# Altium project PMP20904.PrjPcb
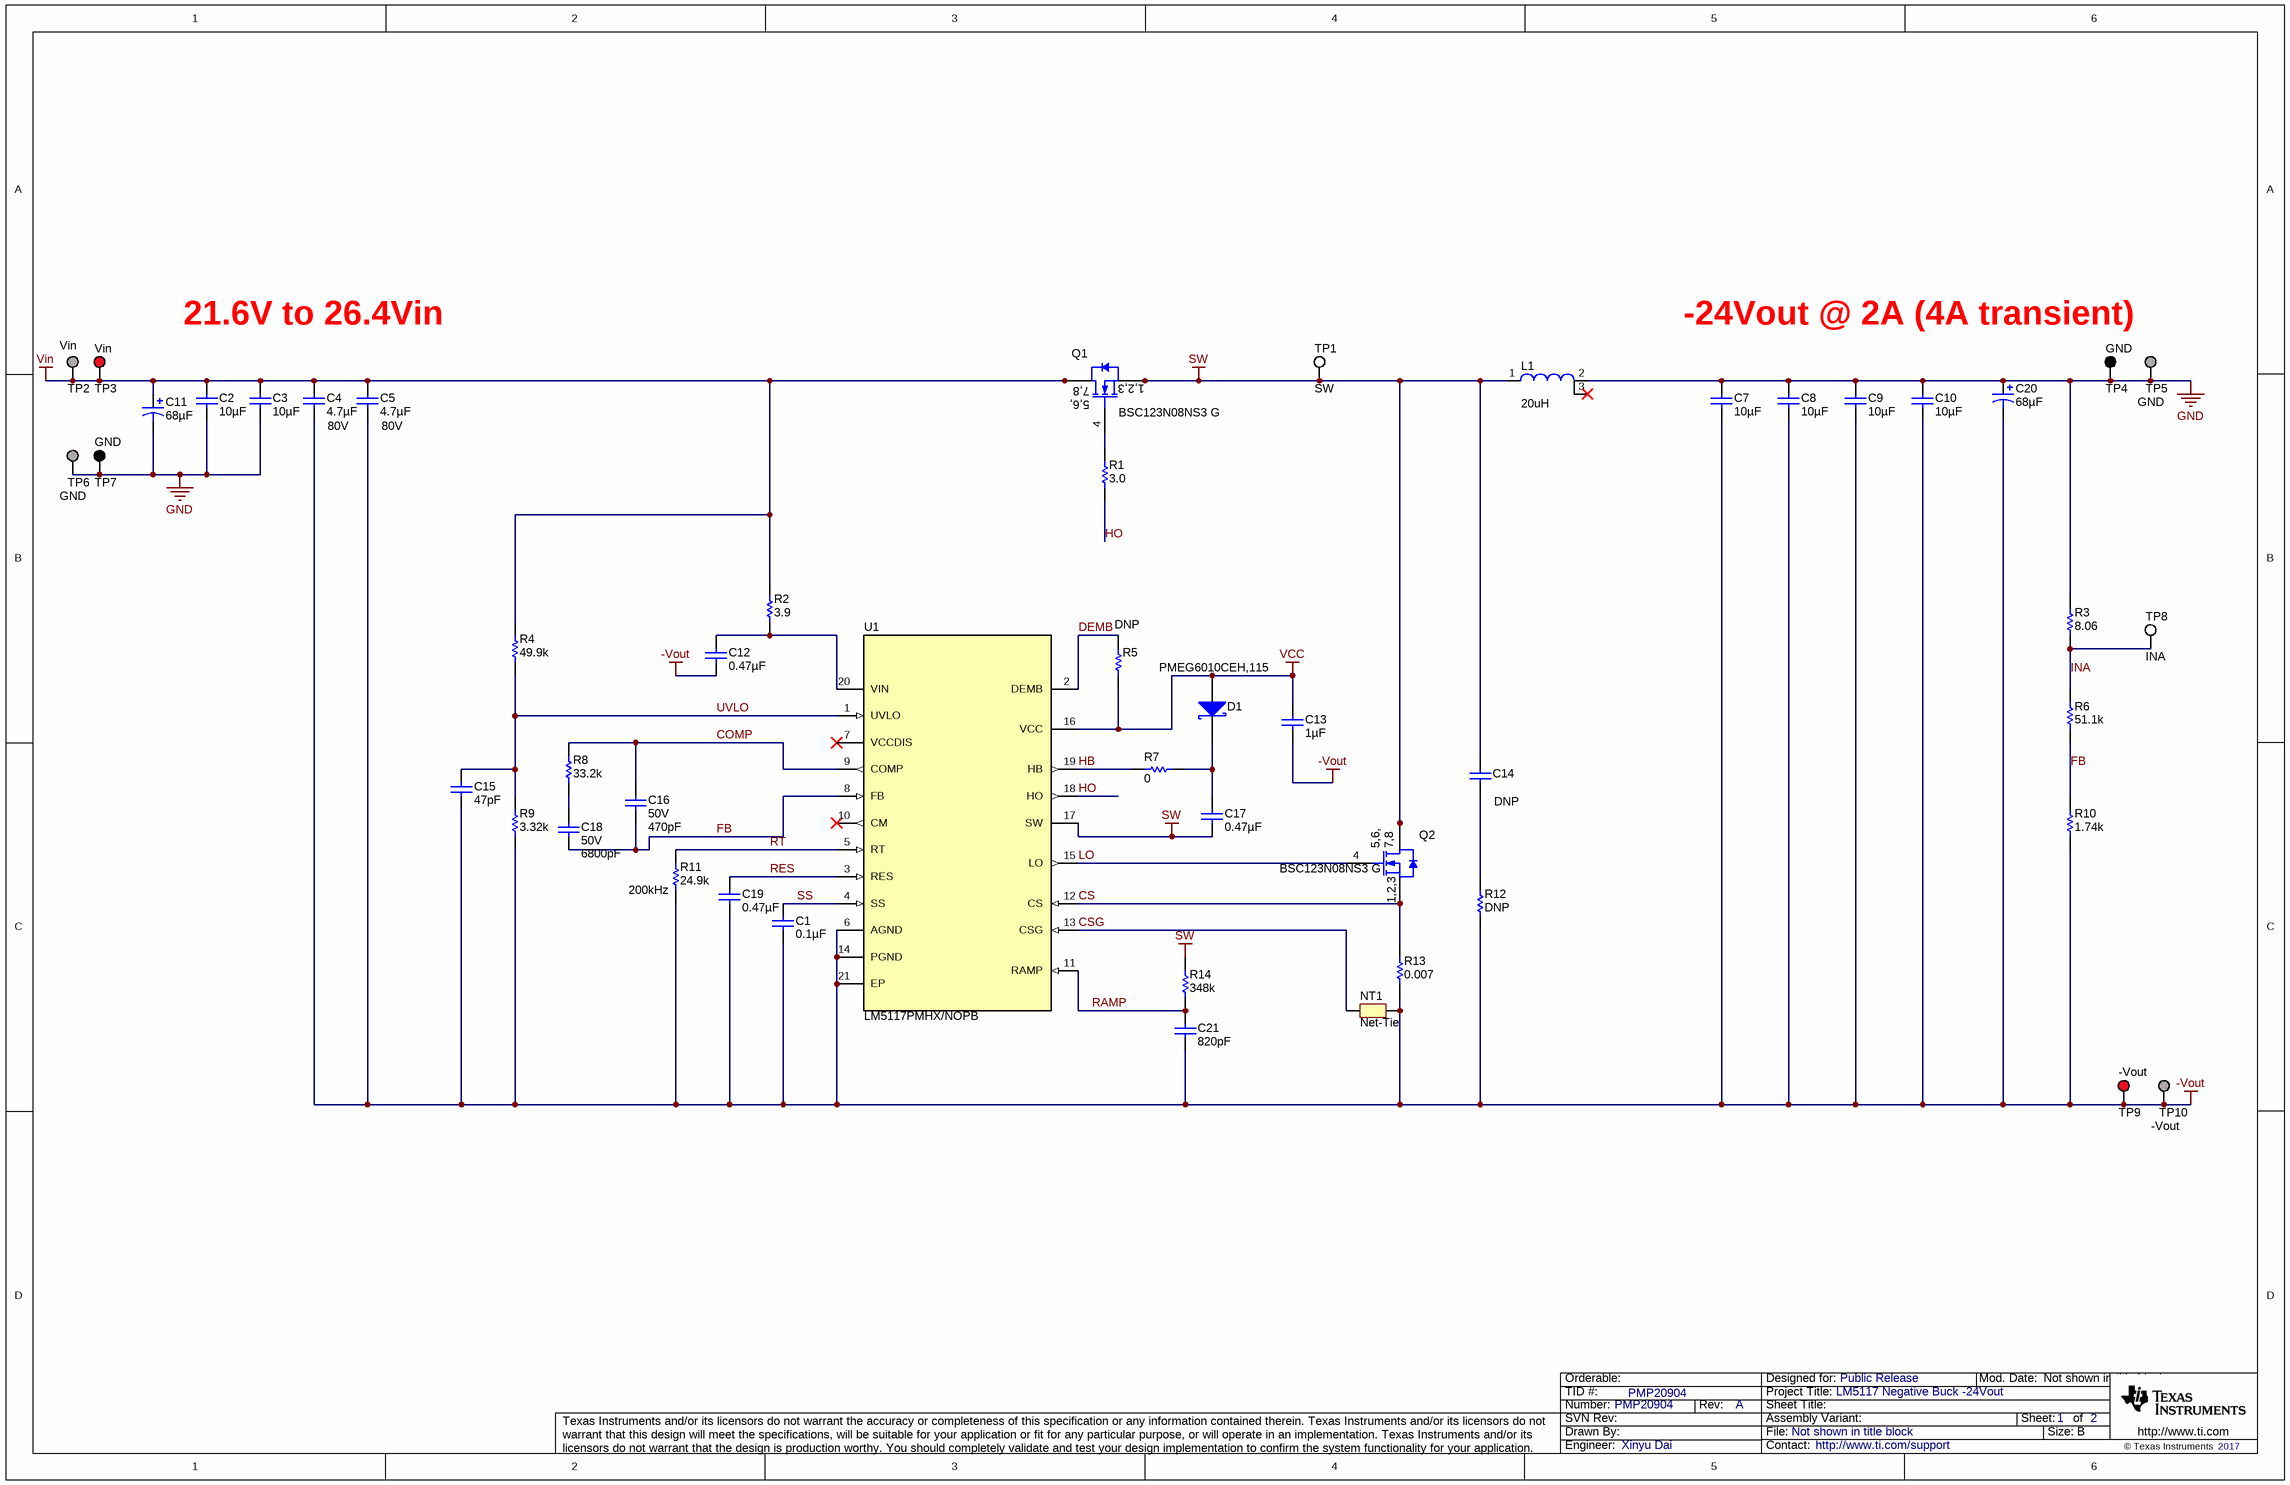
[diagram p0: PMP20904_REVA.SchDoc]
TID: PMP20904; TechSupport: http://www.ti.com/support; SCH_Rev: A; PRJ_Title: LM5117 Negative Buck -24Vout; PRJ_Number: PMP20904; PRJ_Engineer: Xinyu Dai; PRJ_Customer: Public Release; PCB_Rev: A; PCB_Layout: Xinyu Dai; CopyrightYear: 2017
2 sheets, 64 parts. Net scope: global (net labels, ports and power ports of the same name join across sheets).
Board file: PMP20904_REVA.PcbDoc
Sheets:
  PMP20904_REVA.SchDoc
  PMP20904_REVA_Hardware.SchDoc

## Sheet PMP20904_REVA.SchDoc
size 431 x 279 mm; Date: Not shown in title block; ApprovedBy: Not shown in title block; CheckedBy: Not shown in title block; Author: Not shown in title block; CompanyName: Not shown in title block; Engineer: Not shown in title block; Organization: Not shown in title block; Address1: Not shown in title block; Address2: Not shown in title block; Address3: Not shown in title block; Address4: Not shown in title block; DocumentNumber: 1; Revision: Use project parameter SCH_Rev; SheetNumber: 1; SheetTotal: 2; PageSetup: Record=PageOptions¦CenterHorizontal=True¦CenterVertical=True¦PrintScale=1.00¦XCorrection=1.00¦YCorrection=1.00¦PrintKind=0¦BorderSize=5000000¦LeftOffset=0¦BottomOffset=0¦Orientation=2¦PaperLength=1000¦PaperWidth=1000¦Scale=100¦PaperSource=15¦PrintQuality=600¦MediaType=1¦DitherType=10¦PaperKind=Letter¦PrintScaleMode=1

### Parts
C1  ValueDisplayed: 0.1µF  [0603L]  (hidden comment: GRM188R71E104KA01D)
C2  ValueDisplayed: 10µF  [1210L]  (hidden comment: UMK325AB7106KM-T)
C3  ValueDisplayed: 10µF  [1210L]  (hidden comment: UMK325AB7106KM-T)
C4  ValueDisplayed: 4.7µF  Value2: 80V  [1210L]  (hidden comment: GRM32ER71K475KE14L)
C5  ValueDisplayed: 4.7µF  Value2: 80V  [1210L]  (hidden comment: GRM32ER71K475KE14L)
C7  ValueDisplayed: 10µF  [1210L]  (hidden comment: UMK325AB7106KM-T)
C8  ValueDisplayed: 10µF  [1210L]  (hidden comment: UMK325AB7106KM-T)
C9  ValueDisplayed: 10µF  [1210L]  (hidden comment: UMK325AB7106KM-T)
C10  ValueDisplayed: 10µF  [1210L]  (hidden comment: UMK325AB7106KM-T)
C11  ValueDisplayed: 68µF  [SM_RADIAL_6.3BMM]  (hidden comment: UUD1V680MCL1GS)
C12  ValueDisplayed: 0.47µF  [0603L]  (hidden comment: CGA3E3X7R1H474M080AE)
C13  ValueDisplayed: 1µF  [0603L]  (hidden comment: GRM188R71C105KE15D)
C14  DNP  [0805L]
C15  ValueDisplayed: 47pF  [0603L]  (hidden comment: GRM1885C1H470JA01D)
C16  VDC_V: 50V  ValueDisplayed: 470pF  [0603L]  (hidden comment: GRM1885C1H471JA01D)
C17  ValueDisplayed: 0.47µF  [0603L]  (hidden comment: CGA3E3X7R1H474M080AE)
C18  VDC_V: 50V  ValueDisplayed: 6800pF  [0603L]  (hidden comment: GRM188R71H682KA01D)
C19  ValueDisplayed: 0.47µF  [0603L]  (hidden comment: CGA3E3X7R1H474M080AE)
C20  ValueDisplayed: 68µF  [SM_RADIAL_6.3BMM]  (hidden comment: UUD1V680MCL1GS)
C21  ValueDisplayed: 820pF  [0603L]  (hidden comment: GRM1885C1H821JA01D)
D1  PMEG6010CEH,115  [SOD-123F]
L1  ValueDisplayed: 20uH  [B82559_1420]  (hidden comment: B82559A203A20)
NT1  Net-Tie  [Net-Tie_10mil]  (net tie, no BOM)
Q1  BSC123N08NS3 G  [PG-TDSON-8]
Q2  BSC123N08NS3 G  [PG-TDSON-8]
R1  ValueDisplayed: 3.0  [0603L]  (hidden comment: CRCW06033R00JNEA)
R2  ValueDisplayed: 3.9  [0603L]  (hidden comment: CRCW06033R90JNEA)
R3  ValueDisplayed: 8.06  [0603L]  (hidden comment: CRCW06038R06FKEA)
R4  ValueDisplayed: 49.9k  [0603L]  (hidden comment: CRCW060349K9FKEA)
R5  DNP  [0603L]
R6  ValueDisplayed: 51.1k  [0603L]  (hidden comment: CRCW060351K1FKEA)
R7  ValueDisplayed: 0  [0603L]  (hidden comment: CRCW06030000Z0EA)
R8  ValueDisplayed: 33.2k  [0603L]  (hidden comment: CRCW060333K2FKEA)
R9  ValueDisplayed: 3.32k  [0603L]  (hidden comment: CRCW06033K32FKEA)
R10  ValueDisplayed: 1.74k  [0603]  (hidden comment: CRCW06031K74FKEA)
R11  ValueDisplayed: 24.9k  [0603L]  (hidden comment: CRCW060324K9FKEA)
R12  DNP  [1206L]
R13  ValueDisplayed: 0.007  [PE1206]  (hidden comment: PE1206FRF470R007L)
R14  ValueDisplayed: 348k  [0603L]  (hidden comment: CRCW0603348KFKEA)
TP1  SW  [Keystone5002]
TP2  Vin  [Keystone1502-2]
TP3  Vin  [Keystone5000]
TP4  GND  [Keystone5001]
TP5  GND  [Keystone1502-2]
TP6  GND  [Keystone1502-2]
TP7  GND  [Keystone5001]
TP8  INA  [Keystone5002]
TP9  -Vout  [Keystone5000]
TP10  -Vout  [Keystone1502-2]
U1  LM5117PMHX/NOPB  [PWP0020A_N]

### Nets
-Vout: C1.2 C4.2 C5.2 C7.2 C8.2 C9.2 C10.2 C12.2 C13.2 C15.2 C19.2 C20.2(-) C21.2 NT1.1 R9.1 R10.1 R11.1 R12.1 R13.1 TP9.1 TP10.1 U1.6(AGND) U1.14(PGND) U1.21(EP)
GND: C2.2 C3.2 C7.1 C8.1 C9.1 C10.1 C11.2(-) C20.1(+) L1.2 R3.2 TP4.1 TP5.1 TP6.1 TP7.1
SW: C14.1 C17.2 L1.1 Q1.1(S) Q1.2(S) Q1.3(S) Q2.5(D) Q2.6(D) Q2.7(D) Q2.8(D) Q2.9(D) R14.2 TP1.1 U1.17(SW)
VCC: C13.1 D1.2(A) R5.1 U1.16(VCC)
Vin: C2.1 C3.1 C4.1 C5.1 C11.1(+) Q1.5(D) Q1.6(D) Q1.7(D) Q1.8(D) Q1.9(D) R2.2 R4.2 TP2.1 TP3.1
COMP: C16.1 R8.1 U1.9(COMP)
CS: Q2.1(S) Q2.2(S) Q2.3(S) R13.2 U1.12(CS)
CSG: NT1.2 U1.13(CSG)
DEMB: R5.2 U1.2(DEMB)
FB: C16.2 C18.2 R6.1 R10.2 U1.8(FB)
HB: R7.2 U1.19(HB)
HO: R1.1 U1.18(HO)
INA: R3.1 R6.2 TP8.1
LO: Q2.4(G) U1.15(LO)
RAMP: C21.1 R14.1 U1.11(RAMP)
RES: C19.1 U1.3(RES)
RT: R11.2 U1.5(RT)
SS: C1.1 U1.4(SS)
UVLO: C15.1 R4.1 R9.2 U1.1(UVLO)
NetC12_1: C12.1 R2.1 U1.20(VIN)
NetC14_2: C14.2 R12.2
NetC17_1: C17.1 D1.1(K) R7.1
NetC18_1: C18.1 R8.2
NetQ1_4: Q1.4(G) R1.2

Not connected (* = marked no-connect by the designer): L1 3*; U1 7(VCCDIS)* 10(CM)*

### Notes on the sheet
- 21.6V to 26.4Vin
- -24Vout @ 2A (4A transient)
- (near R11) 200kHz

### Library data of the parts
C1 = GRM188R71E104KA01D: CAP, CERM, 0.1 µF, 25 V, +/- 10%, X7R, 0603; Manufacturer: MuRata; Polarized: N; CompType: Capacitor; Value: 0.1uF; U/M: EA; Cap_F: 0.0000001; Tolerance_%: 10; Value1: Unknown; VDC_V: 25; Value2: 25V; TaMin_C: -55; TaMax_C: 125; Cap_Case: 0603; SizeArea_mm2: 1.28; SizeAreaWB_mm2: 4.68; SizeX_mm: 1.6; SizeY_mm: 0.8; SizeZ_mm: 1; AEC Category: Q200
C2 C3 C7-C10 = UMK325AB7106KM-T: CAP, CERM, 10 µF, 50 V, +/- 10%, X7R, 1210; Manufacturer: Taiyo Yuden; Polarized: N; CompType: Capacitor; Value: 10uF; U/M: EA; Cap_F: 0.00001; Tolerance_%: 10; Value1: Unknown; VDC_V: 50; Value2: 50V; TaMin_C: -55; TaMax_C: 125; Cap_Case: 1210; SizeArea_mm2: 8; SizeAreaWB_mm2: 14.7; SizeX_mm: 3.2; SizeY_mm: 2.5; SizeZ_mm: 2.8; AEC Category: Q200
C4 C5 = GRM32ER71K475KE14L: CAP, CERM, 4.7 µF, 80 V, +/- 10%, X7R, 1210; Manufacturer: MuRata; Polarized: N; CompType: Capacitor; Value: 4.7uF; U/M: EA; Cap_F: 0.0000047; Tolerance_%: 10; Value1: Unknown; VDC_V: 80; TaMin_C: -55; TaMax_C: 125; Cap_Case: 1210; SizeArea_mm2: 8; SizeAreaWB_mm2: 14.7; SizeX_mm: 3.2; SizeY_mm: 2.5; SizeZ_mm: 2.7; AEC Category: Q200
C11 C20 = UUD1V680MCL1GS: CAP, AL, 68 µF, 35 V, +/- 20%, 0.34 ohm, SMD; Manufacturer: Nichicon; Polarized: Y; CompType: Capacitor; Value: 68uF; U/M: EA; Cap_F: 0.000068; Tolerance_%: 20; VDC_V: 35; Value2: 35V; ESR_ohm: 0.34; IRMS_A: 0.28; TaMin_C: -55; TaMax_C: 105; Cap_Case: 6.3x7.7; SizeAreaWB_mm2: 79.98; SizeArea_mm2: 48.18; SizeX_mm: 7.3; SizeY_mm: 6.6; SizeZ_mm: 7.7; AEC Category: Q200
C12 C17 C19 = CGA3E3X7R1H474M080AE: CAP, CERM, 0.47 µF, 50 V, +/- 20%, X7R, AEC-Q200 Grade 1, 0603; Manufacturer: TDK; Polarized: N; CompType: Capacitor; Value: 0.47uF; U/M: EA; Cap_F: 0.00000047; Tolerance_%: 20; Value1: Unknown; VDC_V: 50; Value2: 50V; TaMin_C: -55; TaMax_C: 125; Cap_Case: 0603; SizeArea_mm2: 1.28; SizeAreaWB_mm2: 4.68; SizeX_mm: 1.6; SizeY_mm: 0.8; SizeZ_mm: 1; AEC Category: Q200; AEC Qualified: Y
C13 = GRM188R71C105KE15D: CAP, CERM, 1 µF, 16 V, +/- 10%, X7R, 0603; Manufacturer: MuRata; Polarized: N; CompType: Capacitor; Value: 1uF; U/M: EA; Cap_F: 0.000001; Tolerance_%: 10; Value1: Unknown; VDC_V: 16; Value2: 16V; TaMin_C: -55; TaMax_C: 125; Cap_Case: 0603; SizeArea_mm2: 1.28; SizeAreaWB_mm2: 4.68; SizeX_mm: 1.6; SizeY_mm: 0.8; SizeZ_mm: 1; AEC Category: Q200
C14 = GRM2165C2A101JA01D: CAP, CERM, 100 pF, 100 V, +/- 5%, C0G/NP0, 0805; Manufacturer: MuRata; Polarized: N; CompType: Capacitor; Value: 100pF; U/M: EA; Cap_F: 0.0000000001; Tolerance_%: 5; Value1: Unknown; VDC_V: 100; Value2: 100V; TaMin_C: -55; TaMax_C: 125; Cap_Case: 0805; SizeArea_mm2: 2.5; SizeAreaWB_mm2: 6.75; SizeX_mm: 2; SizeY_mm: 1.25; SizeZ_mm: 1.45; AEC Category: Q200
C15 = GRM1885C1H470JA01D: CAP, CERM, 47 pF, 50 V, +/- 5%, C0G/NP0, 0603; Manufacturer: MuRata; Polarized: N; CompType: Capacitor; Value: 47pF; U/M: EA; Cap_F: 0.000000000047; Tolerance_%: 5; Value1: Unknown; VDC_V: 50; Value2: 50V; TaMin_C: -55; TaMax_C: 125; Cap_Case: 0603; SizeArea_mm2: 1.28; SizeAreaWB_mm2: 4.68; SizeX_mm: 1.6; SizeY_mm: 0.8; SizeZ_mm: 1; AEC Category: Q200
C16 = CMP-0007221-2: CAP, CERM, 470 pF, 50 V, +/- 5%, C0G/NP0, 0603; Manufacturer: MuRata; TaMin_C: -55°C; Polarized: N; SizeAreaWB_mm2: 4.68; Value1: Unknown; U/M: EA; Value: 470pF; TaMax_C: 125°C; SizeZ_mm: 1; SizeX_mm: 1.6; SizeY_mm: 0.8; Cap_Case: 0603; SizeArea_mm2: 1.28; CompType: Capacitor; AEC Category: Q200
C18 = CMP-0007462-2: CAP, CERM, 6800 pF, 50 V, +/- 10%, X7R, 0603; Manufacturer: MuRata; TaMin_C: -55°C; Polarized: N; SizeAreaWB_mm2: 4.68; Value1: Unknown; U/M: EA; Value: 6800pF; TaMax_C: 125°C; SizeZ_mm: 1; SizeX_mm: 1.6; SizeY_mm: 0.8; Cap_Case: 0603; SizeArea_mm2: 1.28; CompType: Capacitor; Cap_F: 6.8nF; AEC Category: Q200
C21 = GRM1885C1H821JA01D: CAP, CERM, 820 pF, 50 V, +/- 5%, C0G/NP0, 0603; Manufacturer: MuRata; Polarized: N; CompType: Capacitor; Value: 820pF; U/M: EA; Cap_F: 0.00000000082; Tolerance_%: 5; Value1: Unknown; VDC_V: 50; Value2: 50V; TaMin_C: -55; TaMax_C: 125; Cap_Case: 0603; SizeArea_mm2: 1.28; SizeAreaWB_mm2: 4.68; SizeX_mm: 1.6; SizeY_mm: 0.8; SizeZ_mm: 1; AEC Category: Q200
D1 = PMEG6010CEH,115: Diode, Schottky, 60 V, 1 A, SOD-123F; Manufacturer: Nexperia; U/M: EA; Vf_V: 0.57; Value: 60V; Value1: 1A; Value2: 0.57V; Io_A: 1; Vr_V: 60; TJmax_C: 150; SizeAreaWB_mm2: 11.7; SizeArea_mm2: 5.6; SizeX_mm: 3.5; SizeY_mm: 1.6; SizeZ_mm: 1.1; AEC Category: Q101
L1 = CMP-0062443-2: Inductor, Wirewound, Ferrite, 20 uH, 14.3 A, 0.0064 ohm, AEC-Q200 Grade 0, SMD; Manufacturer: TDK; Isat: 14.3A @ 10% inductance drop; Green_Lifecycle: Not Set; SizeAreaWB_mm2: 583.2; DCR_ohm: 6.4m; Green_REACh: Incomplete; Value: 20uH; Imax_A: 14.3A; SizeZ_mm: 14.5; SizeX_mm: 22; SizeY_mm: 22.3; SizeArea_mm2: 490.6; Ind_H: 20µH; AEC Qualified: Y; AEC Grade: 0; AEC Category: Q200
NT1 = Net-Tie: Single point connection between nets.; SymbolCreator: codlsc
Q1 Q2 = BSC123N08NS3 G: MOSFET, N-CH, 80 V, 55 A, PG-TDSON-8; Manufacturer: Infineon Technologies; Alternate Manufacturer: None; U/M: EA; ChType: N; Value: 80V; VdsMax_V: 80; Value1: ? ohm; Value2: 19 nC; QgTyp_nC: 19; Vgs_V: 20; IdsMax_A: 55; SizeAreaWB_mm2: 55.131; SizeArea_mm2: 29.351; SizeX_mm: 5.99; SizeY_mm: 4.9; SizeZ_mm: 1.12; AEC Category: Q101; Green_Lifecycle: Active; Green_REACh: Passed
R1 = CRCW06033R00JNEA: RES, 3.0, 5%, 0.1 W, 0603; Manufacturer: Vishay-Dale; CompType: Resistor; Value: 3.0; Res_ohm: 3; Value_Code: 3R00; Tolerance_%: 5; Power_W: 0.1; Value2: 0.1W; VDC_V: 75; TempCo: 200 ppm/C; SizeArea_mm2: 1.28; SizeX_mm: 1.6; SizeY_mm: 0.8; SizeZ_mm: 1; EIA_Code: E24; U/M: EA; AEC Category: Q200; Green_Lifecycle: Active; Green_REACh: Passed
R2 = CRCW06033R90JNEA: RES, 3.9, 5%, 0.1 W, 0603; Manufacturer: Vishay-Dale; CompType: Resistor; Value: 3.9; Value_Code: 3R90; Tolerance_%: 5; Power_W: 0.1; Value2: 0.1W; VDC_V: 75; TempCo: 200 ppm/C; SizeArea_mm2: 1.28; SizeX_mm: 1.6; SizeY_mm: 0.8; SizeZ_mm: 1; EIA_Code: E24; U/M: EA; AEC Category: Q200
R3 = CRCW06038R06FKEA: RES, 8.06, 1%, 0.1 W, 0603; Manufacturer: Vishay-Dale; CompType: Resistor; Value: 8.06; Value_Code: 8R06; Tolerance_%: 1; Power_W: 0.1; Value2: 0.1W; VDC_V: 75; TempCo: 100 ppm/C; SizeArea_mm2: 1.28; SizeX_mm: 1.6; SizeY_mm: 0.8; EIA_Code: E96; U/M: EA; AEC Category: Q200
R4 R5 = CRCW060349K9FKEA: RES, 49.9 k, 1%, 0.1 W, 0603; Manufacturer: Vishay-Dale; CompType: Resistor; Value: 49.9k; Res_ohm: 49900; Value_Code: 49k9; Tolerance_%: 1; Power_W: 0.1; Value2: 0.1W; VDC_V: 75; TempCo: 100 ppm/C; SizeArea_mm2: 1.28; SizeX_mm: 1.6; SizeY_mm: 0.8; EIA_Code: E96; U/M: EA; AEC Category: Q200
R6 = CRCW060351K1FKEA: RES, 51.1 k, 1%, 0.1 W, 0603; Manufacturer: Vishay-Dale; CompType: Resistor; Value: 51.1k; Res_ohm: 51100; Value_Code: 51k1; Tolerance_%: 1; Power_W: 0.1; Value2: 0.1W; VDC_V: 75; TempCo: 100 ppm/C; SizeArea_mm2: 1.28; SizeX_mm: 1.6; SizeY_mm: 0.8; EIA_Code: E96; U/M: EA; AEC Category: Q200; Green_Lifecycle: Active; Green_REACh: Passed
R7 = CRCW06030000Z0EA: RES, 0, 5%, 0.1 W, 0603; Manufacturer: Vishay-Dale; CompType: Resistor; Value: 0; Value_Code: 0000; Tolerance_%: 5; Power_W: 0.1; Value2: 0.1W; VDC_V: 75; TempCo: 200 ppm/C; SizeArea_mm2: 1.28; SizeX_mm: 1.6; SizeY_mm: 0.8; SizeZ_mm: 1; EIA_Code: E24; U/M: EA; AEC Category: Q200; Green_Lifecycle: Active; Green_REACh: Passed
R8 = CRCW060333K2FKEA: RES, 33.2 k, 1%, 0.1 W, 0603; Manufacturer: Vishay-Dale; CompType: Resistor; Value: 33.2k; Res_ohm: 33200; Value_Code: 33k2; Tolerance_%: 1; Power_W: 0.1; Value2: 0.1W; VDC_V: 75; TempCo: 100 ppm/C; SizeArea_mm2: 1.28; SizeX_mm: 1.6; SizeY_mm: 0.8; EIA_Code: E96; U/M: EA; AEC Category: Q200; Green_Lifecycle: Active; Green_REACh: Passed
R9 = CRCW06033K32FKEA: RES, 3.32 k, 1%, 0.1 W, 0603; Manufacturer: Vishay-Dale; CompType: Resistor; Value: 3.32k; Res_ohm: 3320; Value_Code: 3k32; Tolerance_%: 1; Power_W: 0.1; Value2: 0.1W; VDC_V: 75; TempCo: 100 ppm/C; SizeArea_mm2: 1.28; SizeX_mm: 1.6; SizeY_mm: 0.8; EIA_Code: E96; U/M: EA; AEC Category: Q200
R10 = CRCW06031k74FKEA: RES, 1.74 k, 1%, 0.1 W, 0603; Manufacturer: Vishay-Dale; CompType: Resistor; Value: 1.74k; Res_ohm: 1740; Value_Code: 1k74; Tolerance_%: 1; Power_W: 0.1; Value2: 0.1W; VDC_V: 75; TempCo: 100 ppm/C; SizeArea_mm2: 1.28; SizeX_mm: 1.6; SizeY_mm: 0.8; EIA_Code: E96; U/M: EA; AEC Category: Q200; Green_Lifecycle: Active; Green_REACh: Passed
R11 = CRCW060324K9FKEA: RES, 24.9 k, 1%, 0.1 W, 0603; Manufacturer: Vishay-Dale; CompType: Resistor; Value: 24.9k; Res_ohm: 24900; Value_Code: 24k9; Tolerance_%: 1; Power_W: 0.1; Value2: 0.1W; VDC_V: 75; TempCo: 100 ppm/C; SizeArea_mm2: 1.28; SizeX_mm: 1.6; SizeY_mm: 0.8; EIA_Code: E96; U/M: EA; AEC Category: Q200; Green_Lifecycle: Active; Green_REACh: Passed
R12 = CRCW120610R0JNEA: RES, 10, 5%, 0.25 W, 1206; Manufacturer: Vishay-Dale; CompType: Resistor; Value: 10; Value_Code: 10R0; Tolerance_%: 5; Power_W: 0.25; Value2: 0.25W; VDC_V: 200; TempCo: 200 ppm/C; SizeArea_mm2: 5.12; SizeX_mm: 3.2; SizeY_mm: 1.6; SizeZ_mm: 1.35; EIA_Code: E24; U/M: EA; AEC Category: Q200
R13 = CMP-0017834-2: RES, 0.007, 1%, 1 W, AEC-Q200 Grade 0, 1206; Manufacturer: Yageo America; Power_W: 1W; TempCo: 100 ppm/C; Value_Code: 7L000; U/M: EA; Value: 0.007; EIA_Code: E96; Res_ohm: 7m; SizeX_mm: 3.2; SizeY_mm: 1.6; SizeZ_mm: 0.89; SizeArea_mm2: 5.12; CompType: Resistor; AEC Qualified: Y; AEC Grade: 0; AEC Category: Q200
R14 = CRCW0603348KFKEA: RES, 348 k, 1%, 0.1 W, 0603; Manufacturer: Vishay-Dale; CompType: Resistor; Value: 348k; Res_ohm: 348000; Tolerance_%: 1; Power_W: 0.1; Value2: 0.1W; VDC_V: 75; TempCo: 100 ppm/C; SizeArea_mm2: 1.28; SizeX_mm: 1.6; SizeY_mm: 0.8; EIA_Code: E96; U/M: EA; AEC Category: Q200; Green_Lifecycle: Active; Green_REACh: Passed
TP1 TP8 = 5002: Test Point, TH, Miniature, White; Manufacturer: Keystone; Alternate Manufacturer: Any; Alternate PartNumber: Equivalent; CompType: Test Point Loop; U/M: EA
TP2 TP5 TP6 TP10 = 1502-2: Terminal, Turret, TH, Double; Manufacturer: Keystone; CompType: Turret Terminal
TP3 TP9 = 5000: Test Point, TH, Miniature, Red; Manufacturer: Keystone; Alternate Manufacturer: Any; Alternate PartNumber: Equivalent; CompType: Test Point Loop; U/M: EA
TP4 TP7 = 5001: Test Point, TH, Miniature, Black; Manufacturer: Keystone; Alternate Manufacturer: Any; Alternate PartNumber: Equivalent; CompType: Test Point Loop; U/M: EA
U1 = LM5117PMHX/NOPB: 5.5-65V Wide Vin, Current Mode Synchronous Buck Controller with Analog Current Monitor, PWP0020A (TSSOP-20); Alternate PartNumber: LM5117PMHE/NOPB; Manufacturer: Texas Instruments; SymbolCreator: a0411947; SizeArea_mm2: 41.6; SizeAreaWB_mm2: 71.4; SizeX_mm: 6.4; SizeY_mm: 6.5; SizeZ_mm: 1.2; CompType: IC; U/M: EA

## Sheet PMP20904_REVA_Hardware.SchDoc
size 431 x 279 mm; Date: Not shown in title block; ApprovedBy: Not shown in title block; CheckedBy: Not shown in title block; Author: Not shown in title block; CompanyName: Not shown in title block; Engineer: Not shown in title block; Organization: Not shown in title block; Address1: Not shown in title block; Address2: Not shown in title block; Address3: Not shown in title block; Address4: Not shown in title block; DocumentNumber: 2; Revision: Use project parameter SCH_Rev; SheetNumber: 2; SheetTotal: 2; PageSetup: Record=PageOptions¦CenterHorizontal=True¦CenterVertical=True¦PrintScale=1.00¦XCorrection=1.00¦YCorrection=1.00¦PrintKind=0¦BorderSize=5000000¦LeftOffset=0¦BottomOffset=0¦Orientation=2¦PaperLength=1000¦PaperWidth=1000¦Scale=100¦PaperSource=15¦PrintQuality=600¦MediaType=1¦DitherType=10¦PaperKind=Letter¦PrintScaleMode=1
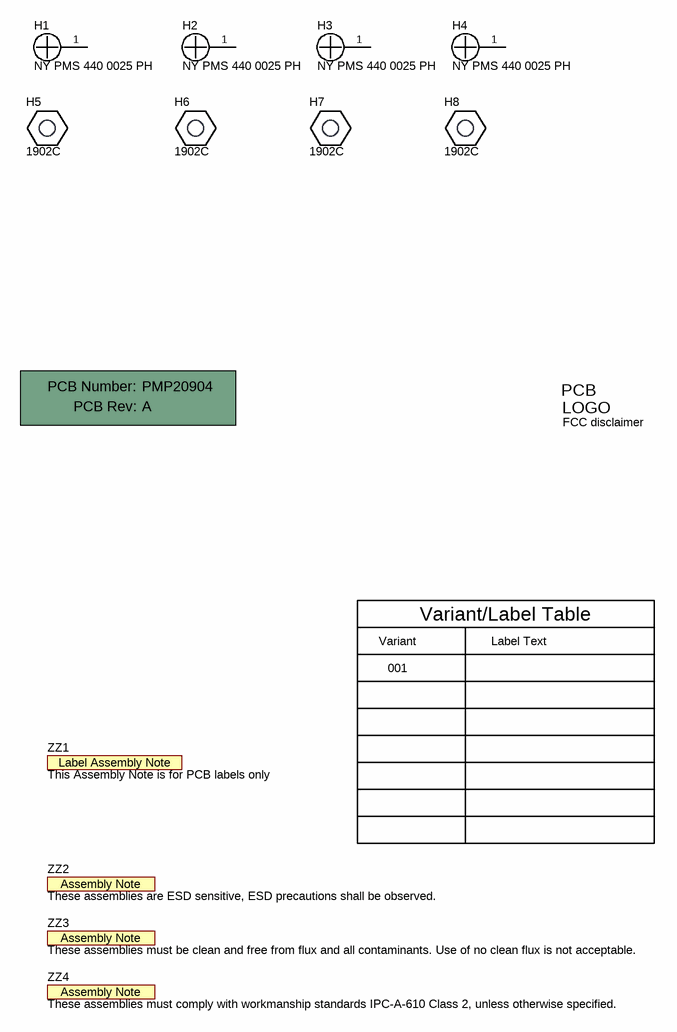
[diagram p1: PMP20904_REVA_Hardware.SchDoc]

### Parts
!PCB1  Printed Circuit Board  (value not drawn)  (mechanical)
H1  NY PMS 440 0025 PH  [NY PMS 440 0025 PH]
H2  NY PMS 440 0025 PH  [NY PMS 440 0025 PH]
H3  NY PMS 440 0025 PH  [NY PMS 440 0025 PH]
H4  NY PMS 440 0025 PH  [NY PMS 440 0025 PH]
H5  1902C  [Keystone_1902C]
H6  1902C  [Keystone_1902C]
H7  1902C  [Keystone_1902C]
H8  1902C  [Keystone_1902C]
Logo2  FCC disclaimer  [FCC_disclaimer]  (no BOM)
ZZ1  This Assembly Note is for PCB labels only  [AssemblyNoteLabel]  (no BOM)
ZZ2  These assemblies are ESD sensitive, ESD precautions shall be observed.  [AssemblyNote]  (no BOM)
ZZ3  These assemblies must be clean and free from flux and all contaminants. Use of no clean flux is not acceptable.  [AssemblyNote]  (no BOM)
ZZ4  These assemblies must comply with workmanship standards IPC-A-610 Class 2, unless otherwise specified.  [AssemblyNote]  (no BOM)

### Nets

Not connected (* = marked no-connect by the designer): H1 1; H2 1; H3 1; H4 1

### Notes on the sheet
- Variant
- Variant/Label Table
- Label Text
- 001

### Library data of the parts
!PCB1 = PCB: Manufacturer: Any; PartNumber: PMP20904; SymbolCreator: a0412235
H1-H4 = NY PMS 440 0025 PH: Machine Screw, Round, #4-40 x 1/4, Nylon, Philips panhead; Manufacturer: B&F Fastener Supply; CompType: Hardware; SymbolCreator: codlsc; U/M: EA
H5-H8 = 1902C: Standoff, Hex, 0.5"L #4-40 Nylon; Manufacturer: Keystone; CompType: Hardware
Logo2 = FCC_disclaimer: SymbolCreator: codlsc
ZZ1 = AssemblyNoteLabel: SymbolCreator: a0412235
ZZ2-ZZ4 = AssemblyNote: SymbolCreator: codlsc

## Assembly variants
001: not fitted C14 R5 R12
